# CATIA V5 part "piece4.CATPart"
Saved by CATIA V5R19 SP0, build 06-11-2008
Part number: Part4
Bounding box of the stored display mesh (mm): x 0 to 30, y -29.152 to 85.15, z 3.259 to 19.259
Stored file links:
  C:\Documents and Settings\ibouchefra\Bureau\projet_II\piece4.CATPart
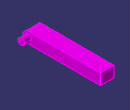
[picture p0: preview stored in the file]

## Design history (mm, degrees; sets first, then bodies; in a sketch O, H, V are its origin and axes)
Body1 (main body)
  Sketch1 on yz-plane, origin (0, 0, 0), H (0, 1, 0), V (0, 0, 1)
    line L1 (-21.152, 19.259) -> (85.1505, 19.259)
    line L2 (85.1505, 19.259) -> (85.1505, 3.259)
    line L3 (85.1505, 3.259) -> (-21.152, 3.259)
    arc A1 centre (-21.152, 11.259) radius 8 from (-21.152, 19.259) to (-21.152, 3.259) ccw
    radius A1 = 8
    horizontal: L1 H, L3 H
    vertical: L2 V
    tangency: A1 L3, L1 A1
  Pad1: profile Sketch1, direction (1, 0, 0), length 20
  Sketch2 on end face of Pad1, origin (20, 0, 0), H (0, 1, 0), V (0, 0, 1)
    circle A1 centre (-21.3369, 11.2201) radius 5
    radius A1 = 5
  Pad2: profile Sketch2, direction (1, 0, 0), length 10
